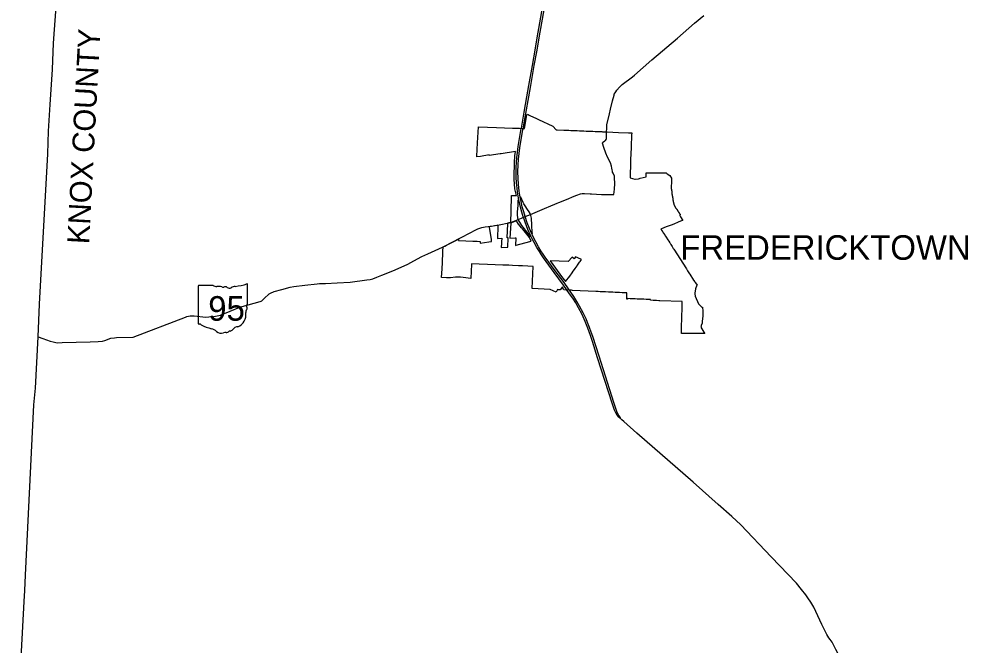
# Model space of a CAD drawing. Extents: x 1851937 to 2123937, y 78841 to 965467.
# Drawn here: x 1929312 to 1972548, y 883220 to 911745 of the extents above; entities that cross this region are included whole.
import ezdxf

# ---------------------------------------------------------------- set-up
doc = ezdxf.new("R2010")
doc.units = 0
for name, color, linetype in [('GM_X_Corporation', 7, 'Continuous'), ('GM_X_Corporation_Text', 7, 'Continuous'), ('GM_X_County', 7, 'Continuous'), ('GM_X_County_Text', 7, 'Continuous'), ('GM_X_State_Location', 7, 'Continuous'), ('GM_X_State_Route', 7, 'Continuous'), ('GM_X_State_Shield', 7, 'Continuous'), ('UT_P_Electric', 7, 'Continuous')]:
    doc.layers.add(name, color=color, linetype=linetype)

msp = doc.modelspace()

# ---------------------------------------------------------------- linework, layer by layer
at = {"layer": 'GM_X_Corporation'}
for points in [[(1948637, 901359), (1948664, 901372), (1948709, 901394), (1948790, 901434), (1949095, 901592), (1949307, 901701), (1949340, 901719), (1949339, 901699), (1949339, 901684), (1949339, 901655), (1949669, 901639), (1949982, 901624), (1950053, 901620), (1950181, 901617), (1950328, 901612), (1950323, 901523), (1950712, 901584), (1950836, 901603), (1950843, 901708), (1950754, 902250), (1950753, 902260), (1950751, 902267), (1950748, 902289), (1950798, 902299), (1950841, 902307), (1950920, 902323), (1950971, 902333), (1951093, 902357), (1951136, 902365), (1951134, 902341), (1951134, 902334), (1951133, 902323), (1951106, 901749), (1951111, 901749), (1951306, 901756), (1951298, 901589), (1951294, 901527), (1951284, 901335), (1951582, 901347), (1951604, 901768), (1951554, 901766), (1951583, 902411), (1951585, 902453), (1951616, 902459), (1951621, 902460), (1951622, 902460), (1951628, 902461), (1951646, 902465), (1951677, 902472), (1951713, 902482), (1951712, 902446), (1951679, 901760), (1951923, 901770), (1951953, 901771), (1951938, 901429), (1951968, 901437), (1952123, 901480), (1952641, 901622), (1952563, 901791), (1952323, 902085), (1952244, 902180), (1952207, 902224), (1952081, 902375), (1952067, 902399), (1951992, 902523), (1951978, 902543), (1951756, 902454), (1951741, 902491), (1951727, 902485), (1951713, 902482), (1951715, 902513), (1951729, 902951), (1951754, 903704), (1951971, 903697), (1951909, 904010), (1951871, 904443), (1951866, 904493), (1951865, 904576), (1951871, 904750), (1951881, 905010), (1951882, 905055), (1951887, 905195), (1951907, 905503), (1951934, 905712), (1951278, 905607), (1951240, 905601), (1950734, 905519), (1950734, 905549), (1950341, 905486), (1950169, 905458), (1950170, 905489), (1950205, 906108), (1950245, 906831), (1951068, 906802), (1951073, 906802), (1951796, 906776), (1951986, 906769), (1952002, 906768), (1952020, 906767), (1952036, 906767), (1952043, 906766), (1952051, 906766), (1952069, 906765), (1952076, 906765), (1952107, 906764), (1952115, 906763), (1952236, 906758), (1952340, 906754), (1952455, 907381), (1952460, 907411), (1952509, 907386), (1952554, 907362), (1952608, 907335), (1952861, 907222), (1952980, 907166), (1953634, 906864), (1953792, 906695), (1953807, 906695), (1953823, 906694), (1953834, 906694), (1954139, 906681), (1954367, 906672), (1954449, 906669), (1954512, 906666), (1954548, 906665), (1954648, 906661), (1954748, 906657), (1954848, 906652), (1954948, 906648), (1955048, 906644), (1955152, 906640), (1955248, 906636), (1955348, 906632), (1955455, 906628), (1955563, 906623), (1955642, 906620), (1955663, 906619), (1955762, 906615), (1955767, 906615), (1955862, 906611), (1955864, 906611), (1955892, 906610), (1955894, 906610), (1955922, 906609), (1955924, 906609), (1955951, 906608), (1955971, 906607), (1956041, 906604), (1956055, 906603), (1956085, 906602), (1956085, 906602), (1956115, 906601), (1956623, 906580), (1957079, 906562), (1957228, 906556), (1957223, 906452), (1957222, 906435), (1957218, 906344), (1957204, 906046), (1957201, 905977), (1957200, 905957), (1957180, 905536), (1957173, 905400), (1957166, 904983), (1957165, 904947), (1957164, 904923), (1957164, 904919), (1957164, 904914), (1957164, 904884), (1957163, 904861), (1957163, 904832), (1957163, 904827), (1957162, 904815), (1957160, 904695), (1957157, 904541), (1957157, 904540), (1957157, 904501), (1957370, 904448), (1957385, 904445), (1957530, 904469), (1957585, 904479), (1957613, 904486), (1957879, 904557), (1957881, 904586), (1957884, 904669), (1957887, 904735), (1958328, 904736), (1958638, 904737), (1958780, 904737), (1958793, 904728), (1958845, 904690), (1958960, 904607), (1959036, 904495), (1959033, 904337), (1959027, 904073), (1959030, 904060), (1959030, 904048), (1959029, 904034), (1959029, 904024), (1959030, 904009), (1959032, 903995), (1959035, 903985), (1959039, 903975), (1959042, 903963), (1959044, 903950), (1959046, 903936), (1959049, 903922), (1959052, 903912), (1959055, 903902), (1959058, 903890), (1959058, 903878), (1959057, 903864), (1959057, 903853), (1959057, 903843), (1959057, 903832), (1959057, 903822), (1959058, 903811), (1959058, 903808), (1959059, 903795), (1959061, 903781), (1959062, 903767), (1959064, 903754), (1959066, 903742), (1959067, 903730), (1959070, 903719), (1959070, 903707), (1959073, 903701), (1959074, 903689), (1959075, 903679), (1959079, 903667), (1959082, 903656), (1959084, 903644), (1959088, 903631), (1959091, 903614), (1959094, 903596), (1959096, 903577), (1959097, 903566), (1959098, 903556), (1959099, 903539), (1959101, 903521), (1959104, 903501), (1959106, 903490), (1959108, 903479), (1959109, 903470), (1959113, 903453), (1959113, 903450), (1959116, 903437), (1959120, 903419), (1959125, 903399), (1959127, 903388), (1959129, 903378), (1959133, 903363), (1959136, 903351), (1959140, 903337), (1959143, 903321), (1959147, 903304), (1959152, 903286), (1959160, 903272), (1959166, 903259), (1959173, 903244), (1959180, 903228), (1959187, 903210), (1959195, 903194), (1959203, 903181), (1959210, 903169), (1959219, 903157), (1959229, 903144), (1959238, 903130), (1959246, 903115), (1959256, 903102), (1959266, 903092), (1959276, 903082), (1959284, 903070), (1959290, 903058), (1959298, 903045), (1959307, 903030), (1959316, 903014), (1959324, 903000), (1959333, 902989), (1959342, 902977), (1959350, 902964), (1959359, 902952), (1959366, 902942), (1959373, 902932), (1959380, 902922), (1959386, 902913), (1959388, 902909), (1959391, 902904), (1959396, 902891), (1959402, 902880), (1959410, 902871), (1959417, 902862), (1959426, 902857), (1959438, 902845), (1959444, 902838), (1959450, 902831), (1959443, 902829), (1959417, 902818), (1959425, 902797), (1959449, 902733), (1959549, 902564), (1959532, 902557), (1959350, 902486), (1959141, 902403), (1959020, 902355), (1958927, 902319), (1958846, 902287), (1958797, 902268), (1958587, 902185), (1958559, 902174), (1958578, 902143), (1958587, 902128), (1958626, 902067), (1958640, 902045), (1958666, 902005), (1958729, 901908), (1958755, 901869), (1958769, 901847), (1958827, 901756), (1958836, 901742), (1958842, 901734), (1958941, 901578), (1958948, 901566), (1958975, 901523), (1959007, 901473), (1959069, 901374), (1959121, 901293), (1959139, 901264), (1959716, 900358), (1959770, 900274), (1959864, 900127), (1959873, 900112), (1960041, 899849), (1960099, 899768), (1960121, 899738), (1960182, 899666), (1960182, 899665), (1960204, 899640), (1960192, 899611), (1960127, 899451), (1960106, 899250), (1960104, 899229), (1960121, 899118), (1960267, 898773), (1960426, 898608), (1960454, 898608), (1960454, 898606), (1960457, 898564), (1960464, 898481), (1960464, 898444), (1960462, 898264), (1960461, 898206), (1960440, 897973), (1960432, 897887), (1960398, 897776), (1960386, 897737), (1960378, 897708), (1960516, 897475), (1960551, 897415), (1960545, 897415), (1959496, 897421), (1959497, 897449), (1959500, 897590), (1959500, 897600), (1959502, 897686), (1959523, 898595), (1959523, 898625), (1959529, 898876), (1958511, 898902), (1958461, 898904), (1958356, 898912), (1958279, 898918), (1958202, 898923), (1958093, 898929), (1958078, 898929), (1958079, 898959), (1957988, 898963), (1957979, 898963), (1957879, 898967), (1957779, 898971), (1957679, 898976), (1957648, 898978), (1957579, 898980), (1957509, 898982), (1957479, 898983), (1957387, 898988), (1957379, 898989), (1957279, 898993), (1957258, 898994), (1957179, 898998), (1957152, 898999), (1957031, 899002), (1957030, 898972), (1956998, 898973), (1956999, 898986), (1957008, 899260), (1956979, 899262), (1956789, 899271), (1956670, 899276), (1956570, 899281), (1956470, 899286), (1956370, 899291), (1956270, 899296), (1956171, 899300), (1956031, 899307), (1955912, 899313), (1955793, 899319), (1955693, 899323), (1955593, 899328), (1954532, 899379), (1954482, 899382), (1954373, 899387), (1954346, 899388), (1954132, 899398), (1954131, 899400), (1954080, 899514), (1954066, 899546), (1953969, 899406), (1953890, 899410), (1953849, 899412), (1953782, 899299), (1953516, 899425), (1952694, 899459), (1952743, 900473), (1952495, 900484), (1952248, 900495), (1952064, 900502), (1951795, 900514), (1951621, 900521), (1951549, 900524), (1951350, 900533), (1950657, 900562), (1950274, 900579), (1949933, 900593), (1949914, 900217), (1949900, 899950), (1949899, 899920), (1949546, 899959), (1949428, 899975), (1949349, 899979), (1949274, 899983), (1949194, 899979), (1948970, 899955), (1948868, 899951), (1948789, 899951), (1948564, 899963), (1948565, 899993), (1948573, 900137), (1948599, 900634), (1948607, 900799), (1948616, 900971), (1948628, 901189), (1948635, 901326)], [(1954667, 900902), (1954612, 900822), (1954515, 900888), (1954325, 900688), (1953507, 900719), (1954076, 899947), (1954157, 899842), (1954213, 899778), (1954402, 900023), (1954518, 900184), (1954565, 900253), (1954576, 900268), (1954654, 900381), (1954735, 900498), (1954749, 900517), (1954751, 900521), (1954848, 900661), (1954851, 900665), (1954877, 900702), (1954934, 900784), (1954906, 900796)]]:
    msp.add_lwpolyline(points, close=True, dxfattribs=at)
at = {"layer": 'GM_X_County'}
msp.add_lwpolyline([(1929312, 880640), (1929553, 885197), (1929580, 885702), (1929614, 886406), (1929993, 894168), (1930061, 894922), (1930184, 897269), (1930245, 898753), (1930619, 905601), (1930664, 906637), (1930732, 907847), (1930837, 909450), (1930890, 910647), (1931167, 914598)], dxfattribs=at)
at = {"layer": 'GM_X_State_Route'}
for p, q in [((1955015, 903794), (1955069, 903791)), ((1951187, 902365), (1951340, 902394)), ((1951594, 902447), (1951644, 902459))]:
    msp.add_line(p, q, dxfattribs=at)
for points in [[(1959307, 910864), (1960088, 911551), (1960505, 911902)], [(1956356, 908014), (1956420, 908271), (1956434, 908312), (1956469, 908379), (1956502, 908433), (1956556, 908501), (1956675, 908641), (1956786, 908756), (1957260, 909110), (1957347, 909188), (1958137, 909891), (1959307, 910864)], [(1956214, 907421), (1956262, 907633), (1956356, 908014)], [(1956089, 906775), (1956093, 906866), (1956100, 906921), (1956214, 907421)], [(1956001, 906192), (1956026, 906213), (1956065, 906255), (1956076, 906284), (1956079, 906319), (1956080, 906593), (1956089, 906775)], [(1955890, 906092), (1955916, 906126), (1955989, 906182), (1956001, 906192)], [(1956382, 904719), (1956358, 904764), (1956346, 904805), (1956332, 904865), (1956327, 904951), (1956308, 905046), (1956258, 905187), (1956122, 905452), (1956041, 905631), (1955949, 905894), (1955890, 906092)], [(1956417, 903741), (1956439, 903990), (1956452, 904242), (1956437, 904500), (1956443, 904588), (1956401, 904683), (1956382, 904719)], [(1953909, 903382), (1954255, 903514), (1954608, 903671), (1954722, 903722), (1954896, 903785), (1954972, 903796), (1955015, 903794)], [(1955069, 903791), (1955334, 903778), (1955397, 903775), (1955853, 903754), (1956124, 903748), (1956417, 903741)], [(1953358, 903157), (1953437, 903191), (1953833, 903353), (1953909, 903382)], [(1952201, 902671), (1952294, 902709), (1952370, 902741), (1952614, 902839), (1953358, 903157)], [(1950828, 902310), (1951090, 902346), (1951187, 902365)], [(1951340, 902394), (1951479, 902421), (1951594, 902447)], [(1951644, 902459), (1951744, 902482), (1952047, 902607), (1952201, 902671)], [(1949394, 901756), (1949925, 902032), (1950041, 902090), (1950211, 902179), (1950302, 902215), (1950397, 902239), (1950546, 902271), (1950828, 902310)], [(1948702, 901400), (1949047, 901573), (1949394, 901756)], [(1933223, 897098), (1933493, 897199), (1933666, 897222), (1933758, 897233), (1934507, 897245), (1936899, 898164), (1936953, 898185), (1937107, 898219), (1937297, 898219), (1937818, 898163), (1937967, 898176), (1938183, 898195), (1938500, 898251), (1939378, 898618), (1940293, 898865), (1940345, 898888), (1940373, 898907), (1940529, 899055), (1940660, 899179), (1940706, 899219), (1940766, 899258), (1940945, 899325), (1941289, 899425), (1941664, 899519), (1941830, 899551), (1942334, 899619), (1942891, 899678), (1943005, 899689), (1943277, 899700), (1943810, 899719), (1944394, 899757), (1945163, 899855), (1945311, 899882), (1945428, 899912), (1945617, 899980), (1945844, 900075), (1946340, 900272), (1946584, 900374), (1947029, 900571), (1947294, 900719), (1947671, 900923), (1947939, 901051), (1948609, 901354), (1948702, 901400)], [(1930185, 897266), (1930393, 897186), (1930732, 897060), (1930867, 897028), (1931053, 896996), (1931276, 896999), (1932551, 897034)], [(1932551, 897034), (1932917, 897049), (1933113, 897072), (1933216, 897095), (1933223, 897098)]]:
    msp.add_lwpolyline(points, dxfattribs=at)
at = {"layer": 'GM_X_State_Shield'}
for p, q in [((1937481, 899577), (1937481, 897876)), ((1938160, 899607), (1937503, 899607)), ((1939723, 898759), (1939723, 899649)), ((1939722, 898759), (1939723, 898759))]:
    msp.add_line(p, q, dxfattribs=at)
for centre, radius, start, end in [((1937507, 899581), 26, 98.1301, 188.1301), ((1938316, 899804), 252, 231.6195, 271.1119), ((1938399, 898652), 904, 80.4867, 94.9883), ((1938605, 899590), 72.7, 219.7921, 297.1024), ((1938711, 899393), 151, 54.4667, 119.1411), ((1938906, 899663), 182, 233.8562, 294.8282), ((1939227, 899087), 478, 97.3462, 120.7689), ((1938924, 901926), 2377, 275.8445, 288.9065), ((1939698, 899652), 25, 351.8621, 97.738), ((1939812, 898386), 169, 136.8065, 186.9296), ((1939717, 898694), 38.6, 107.944, 210.337), ((1939471, 898581), 232, 340.033, 23.6496), ((1939696, 898755), 26.7, 289.6038, 7.7341), ((1939057, 898273), 595, 292.3089, 8.9858), ((1937507, 897872), 26.2, 171.9584, 258.3066), ((1937511, 898046), 200, 267.339, 280.6039), ((1937552, 897778), 72.1, 29.7484, 93.2717), ((1938462, 899306), 1716, 240.4129, 257.1985), ((1937950, 897112), 537, 47.1842, 75.836), ((1938895, 897711), 192, 282.8732, 323.2771), ((1939308, 897399), 326, 94.4031, 142.5768), ((1938531, 897770), 341, 230.7004, 286.2918), ((1938728, 897181), 280, 85.6951, 111.2099), ((1938753, 897642), 182, 268.777, 315.5493), ((1938917, 897477), 51.1, 65.7517, 132.6484)]:
    msp.add_arc(centre, radius, start, end, dxfattribs=at)
at = {"layer": 'UT_P_Electric'}
for points in [[(1952276, 906725), (1952279, 906745), (1952403, 907444), (1952537, 908202), (1952626, 908709), (1952787, 909627), (1952913, 910330), (1953010, 910881), (1953875, 915769), (1953940, 916138), (1953965, 916267), (1953995, 916399), (1954022, 916492), (1954062, 916614), (1954120, 916732), (1954186, 916847), (1954208, 916888), (1954235, 916949)], [(1952328, 907502), (1952451, 908204), (1952541, 908711), (1952702, 909628), (1952828, 910331), (1952924, 910882), (1953789, 915771), (1953854, 916140), (1953879, 916268), (1953909, 916400), (1953936, 916493), (1953977, 916616), (1954039, 916719), (1954114, 916820), (1954190, 916912), (1954235, 916949)], [(1954124, 899619), (1953695, 900190), (1953215, 900857), (1953116, 900997), (1953019, 901148), (1952910, 901331), (1952783, 901555), (1952694, 901724), (1952630, 901856), (1952492, 902155), (1952367, 902484), (1952294, 902709), (1952289, 902727), (1952225, 902939), (1952159, 903177), (1952088, 903498), (1952028, 903857), (1952006, 904032), (1951981, 904279), (1951967, 904538), (1951960, 904779), (1951960, 904984), (1951972, 905226), (1951991, 905412), (1952018, 905671), (1952054, 905937), (1952195, 906748), (1952198, 906768), (1952328, 907502)], [(1952369, 902746), (1952307, 902953), (1952241, 903191), (1952170, 903512), (1952151, 903623), (1952106, 903894), (1952073, 904215), (1952054, 904479), (1952044, 904793), (1952053, 905082), (1952066, 905353), (1952094, 905613), (1952129, 905878), (1952273, 906709), (1952276, 906725)], [(1952088, 903498), (1952039, 903490), (1952033, 903262), (1952015, 902950), (1952015, 902808), (1952018, 902700), (1952026, 902666), (1952032, 902641), (1952047, 902607)], [(1952614, 902839), (1952598, 902880), (1952550, 902954), (1952478, 903067), (1952365, 903236), (1952311, 903324), (1952278, 903389), (1952247, 903455), (1952214, 903527), (1952176, 903627), (1952151, 903623)], [(1952674, 901952), (1952709, 901967), (1952698, 902064), (1952688, 902133), (1952679, 902226), (1952670, 902408), (1952666, 902608), (1952661, 902674), (1952652, 902727), (1952635, 902790), (1952619, 902827), (1952614, 902839)], [(1952047, 902607), (1952058, 902580), (1952085, 902535), (1952113, 902487), (1952156, 902414), (1952210, 902336), (1952496, 901971), (1952556, 901894), (1952591, 901840), (1952630, 901856)], [(1954143, 899733), (1953739, 900275), (1953289, 900889), (1953190, 901029), (1953093, 901180), (1952984, 901363), (1952857, 901587), (1952768, 901756), (1952704, 901888), (1952674, 901952), (1952567, 902202), (1952465, 902462), (1952370, 902741), (1952369, 902746)], [(1956715, 893545), (1956679, 893555), (1956637, 893603), (1956569, 893698), (1956505, 893797), (1956442, 893926), (1956346, 894198), (1955675, 896305), (1955440, 897045), (1955365, 897285), (1955278, 897531), (1955199, 897739), (1955105, 897964), (1954963, 898286), (1954801, 898590), (1954675, 898807), (1954538, 899024), (1954399, 899227), (1954124, 899619)], [(1956616, 893730), (1956552, 893855), (1956497, 894000), (1956407, 894274), (1955737, 896382), (1955453, 897277), (1955386, 897480), (1955307, 897693), (1955219, 897914), (1955146, 898075), (1955014, 898358), (1954852, 898661), (1954727, 898879), (1954589, 899095), (1954450, 899299), (1954175, 899690), (1954143, 899733)], [(1956715, 893545), (1956712, 893576), (1956679, 893623), (1956616, 893730)], [(1965890, 884153), (1965523, 884942), (1965387, 885179), (1965256, 885375), (1965164, 885506), (1964968, 885752), (1964733, 886031), (1963586, 887240), (1962202, 888697), (1961786, 889070), (1961166, 889621), (1960024, 890634), (1957466, 892874), (1956865, 893399), (1956770, 893488), (1956715, 893545)], [(1966626, 882812), (1966519, 883012), (1966430, 883198), (1966386, 883283), (1966355, 883343), (1966314, 883412), (1966266, 883476), (1966213, 883545), (1966115, 883696), (1965948, 884027), (1965890, 884153)]]:
    msp.add_lwpolyline(points, dxfattribs=at)

# ---------------------------------------------------------------- texts
at = {"layer": 'GM_X_Corporation_Text'}
msp.add_text('FREDERICKTOWN', height=1120, rotation=0, dxfattribs=at).set_placement((1959441, 900773))
at = {"layer": 'GM_X_County_Text'}
msp.add_text('KNOX COUNTY', height=1000, rotation=86.961, dxfattribs=at).set_placement((1932503, 901469))
at = {"layer": 'GM_X_State_Location'}
msp.add_text('95', height=1, rotation=0, dxfattribs=at).set_placement((1938592, 898204))
for s in ['s', 'r']:
    msp.add_text(s, height=1, dxfattribs=at).set_placement((1938844, 898276))
at = {"layer": 'GM_X_State_Shield'}
msp.add_text('95', height=1120.7, dxfattribs=at).set_placement((1937934, 897996))

doc.saveas('drawing.dxf')
